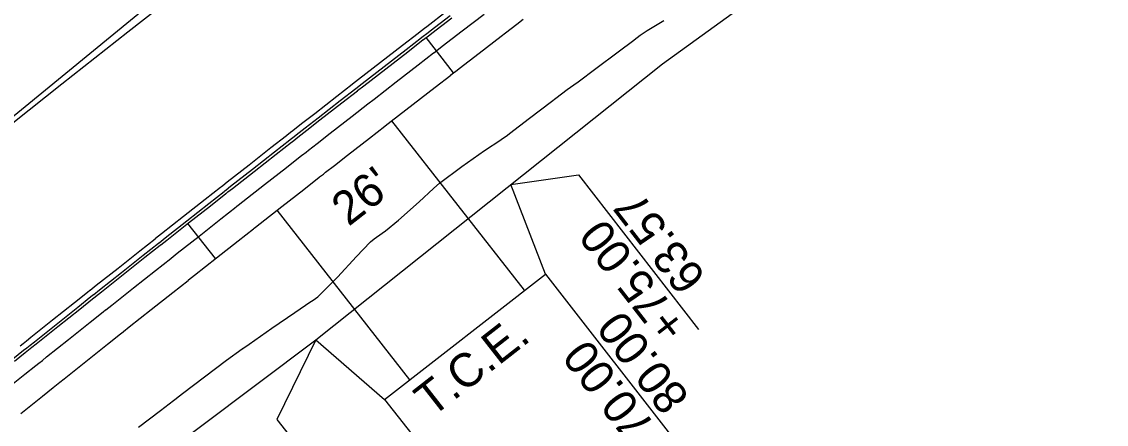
# Model space of a CAD drawing. Extents: x 1147550 to 1149124, y 2017436 to 2018779.
# Drawn here: x 1147906 to 1148099.8, y 2017688.9 to 2017760.9 of the extents above; entities that cross this region are included whole.
import ezdxf

# ---------------------------------------------------------------- set-up
doc = ezdxf.new("R2010")
doc.units = 0
for name, color, linetype in [('S_EDGE_CONCRETE', 7, 'Continuous'), ('S_ELECTRIC_UTILITIES', 7, 'Continuous'), ('S_HEADWALL', 7, 'Continuous'), ('S_IRON_PIN', 7, 'Continuous'), ('S_LANDSCAPING', 7, 'Continuous'), ('S_MAILBOX', 7, 'Continuous'), ('S_SECONDARY_CTL', 7, 'Continuous'), ('S_TELEPHONE_UTILITIES', 7, 'Continuous')]:
    doc.layers.add(name, color=color, linetype=linetype)

msp = doc.modelspace()

# ---------------------------------------------------------------- linework, layer by layer
at = {"layer": 'S_EDGE_CONCRETE'}
msp.add_line((1147825.51, 2017679.08), (1148011.14, 2017831.73), dxfattribs=at)
msp.add_arc((1151464.82, 2013253.76), 5729.58, 124.62946, 129.43332, dxfattribs=at)
at = {"layer": 'S_ELECTRIC_UTILITIES'}
msp.add_lwpolyline([(1147958.55, 2017704.02), (1147951.54, 2017689.76), (1147973.2, 2017662.27)], dxfattribs=at)
at = {"layer": 'S_HEADWALL'}
for p, q in [((1147983.15, 2017751.78), (1147978.22, 2017758.08)), ((1147995.8, 2017712.86), (1147972.09, 2017743.19)), ((1147975.31, 2017696.85), (1147951.6, 2017727.18)), ((1147940.6, 2017718.52), (1147935.68, 2017724.82))]:
    msp.add_line(p, q, dxfattribs=at)
at = {"layer": 'S_IRON_PIN'}
msp.add_line((1147958.55, 2017704.02), (1147970.81, 2017693.3), dxfattribs=at)
msp.add_lwpolyline([(1147970.81, 2017693.3), (1147999.55, 2017715.77), (1147993.38, 2017731.78)], dxfattribs=at)
at = {"layer": 'S_LANDSCAPING'}
for points in [[(1147993.38, 2017731.78), (1148005.46, 2017733.49), (1148026.91, 2017705.83)], [(1147999.55, 2017715.77), (1148024, 2017684.29)], [(1147970.81, 2017693.3), (1147994.96, 2017662.61)]]:
    msp.add_lwpolyline(points, dxfattribs=at)
at = {"layer": 'S_MAILBOX'}
msp.add_lwpolyline([(1147623.68, 2017436.42), (1147751.67, 2017548.43), (1147958.55, 2017704.02), (1148020.45, 2017753.36), (1148124.6, 2017828.73), (1148174.25, 2017853.51), (1148282.74, 2017941.53), (1148421.63, 2018031.39), (1148612.18, 2018197.22), (1148639.91, 2018214.06), (1148753.45, 2018306.48), (1148799.03, 2018350.69)], dxfattribs=at)
at = {"layer": 'S_SECONDARY_CTL'}
msp.add_lwpolyline([(1147926.82, 2017688.36), (1147930.75, 2017691.37), (1147933.11, 2017693.17), (1147933.56, 2017693.51), (1147933.62, 2017693.56), (1147934.69, 2017694.37), (1147938.63, 2017697.37), (1147942.56, 2017700.37), (1147945.37, 2017702.4), (1147945.45, 2017702.46), (1147945.46, 2017702.47), (1147946.6, 2017703.25), (1147950.68, 2017706.07), (1147954.77, 2017708.88), (1147957.64, 2017710.85), (1147957.77, 2017710.94), (1147958.03, 2017711.11), (1147958.86, 2017711.68), (1147962.39, 2017715.2), (1147965.77, 2017718.91), (1147968.21, 2017721.47), (1147968.29, 2017721.53), (1147968.96, 2017722.04), (1147969.37, 2017722.35), (1147970.99, 2017723.48), (1147973.28, 2017725.39), (1147976.97, 2017728.7), (1147979.57, 2017731.09), (1147979.6, 2017731.12), (1147980.63, 2017732.03), (1147980.65, 2017732.04), (1147984.6, 2017735.02), (1147988.66, 2017737.87), (1147991.59, 2017739.8), (1147991.65, 2017739.84), (1147992.77, 2017740.64), (1147993.15, 2017740.93), (1147996.71, 2017743.64), (1148000.65, 2017746.64), (1148001.44, 2017747.24), (1148003.45, 2017748.79), (1148003.45, 2017748.79), (1148004.61, 2017749.62), (1148005.41, 2017750.16), (1148008.59, 2017752.56), (1148012.55, 2017755.53), (1148015.33, 2017757.62), (1148015.4, 2017757.67), (1148016.51, 2017758.5), (1148017.72, 2017759.31), (1148020.73, 2017761.13)], dxfattribs=at)
at = {"layer": 'S_TELEPHONE_UTILITIES'}
for points in [[(1147905.67, 2017702.9), (1147906.24, 2017703.35), (1147906.85, 2017703.83), (1147907.62, 2017704.45), (1147911.5, 2017707.55), (1147915.39, 2017710.65), (1147917.72, 2017712.51), (1147918.17, 2017712.86), (1147918.23, 2017712.91), (1147919.28, 2017713.75), (1147923.18, 2017716.84), (1147927.07, 2017719.93), (1147929.79, 2017722.09), (1147929.87, 2017722.15), (1147929.88, 2017722.16), (1147930.97, 2017723.02), (1147934.87, 2017726.1), (1147938.78, 2017729.18), (1147941.52, 2017731.34), (1147941.65, 2017731.44), (1147941.89, 2017731.63), (1147942.68, 2017732.25), (1147946.59, 2017735.32), (1147950.5, 2017738.39), (1147953.27, 2017740.56), (1147953.35, 2017740.62), (1147954.01, 2017741.14), (1147954.42, 2017741.46), (1147955.99, 2017742.68), (1147958.34, 2017744.52), (1147962.26, 2017747.58), (1147965.05, 2017749.75), (1147965.08, 2017749.78), (1147966.16, 2017750.62), (1147966.18, 2017750.63), (1147970.11, 2017753.68), (1147974.03, 2017756.73), (1147976.81, 2017758.89), (1147976.87, 2017758.93), (1147977.97, 2017759.78), (1147978.34, 2017760.07), (1147981.9, 2017762.82)], [(1147902.67, 2017694.73), (1147906.55, 2017697.83), (1147908.49, 2017699.38), (1147909.05, 2017699.83), (1147909.66, 2017700.32), (1147910.43, 2017700.94), (1147914.31, 2017704.04), (1147918.19, 2017707.13), (1147920.52, 2017708.99), (1147920.97, 2017709.34), (1147921.03, 2017709.39), (1147922.08, 2017710.23), (1147925.97, 2017713.32), (1147929.87, 2017716.4), (1147932.59, 2017718.56), (1147932.66, 2017718.62), (1147932.68, 2017718.63), (1147933.76, 2017719.49), (1147937.66, 2017722.57), (1147941.56, 2017725.64), (1147944.3, 2017727.8), (1147944.43, 2017727.9), (1147944.67, 2017728.09), (1147945.46, 2017728.72), (1147949.37, 2017731.79), (1147953.28, 2017734.85), (1147956.05, 2017737.02), (1147956.12, 2017737.08), (1147956.79, 2017737.6), (1147957.19, 2017737.91), (1147958.76, 2017739.14), (1147961.11, 2017740.97), (1147965.02, 2017744.03), (1147967.81, 2017746.2), (1147967.84, 2017746.23), (1147968.93, 2017747.07), (1147968.94, 2017747.08), (1147972.87, 2017750.13), (1147976.79, 2017753.18), (1147979.57, 2017755.33), (1147979.62, 2017755.37), (1147980.72, 2017756.22), (1147981.09, 2017756.51), (1147984.65, 2017759.26), (1147988.58, 2017762.29)], [(1147904.36, 2017700.57), (1147906.3, 2017702.12), (1147906.86, 2017702.57), (1147907.47, 2017703.05), (1147908.24, 2017703.67), (1147912.13, 2017706.77), (1147916.01, 2017709.87), (1147918.34, 2017711.73), (1147918.79, 2017712.08), (1147918.85, 2017712.13), (1147919.9, 2017712.97), (1147923.8, 2017716.06), (1147927.69, 2017719.15), (1147930.41, 2017721.3), (1147930.49, 2017721.36), (1147930.51, 2017721.37), (1147931.59, 2017722.23), (1147935.49, 2017725.31), (1147939.4, 2017728.39), (1147942.13, 2017730.55), (1147942.26, 2017730.65), (1147942.51, 2017730.84), (1147943.3, 2017731.47), (1147947.21, 2017734.54), (1147951.12, 2017737.61), (1147953.89, 2017739.77), (1147953.96, 2017739.83), (1147954.63, 2017740.35), (1147955.04, 2017740.67), (1147956.6, 2017741.9), (1147958.95, 2017743.73), (1147962.87, 2017746.79), (1147965.66, 2017748.96), (1147965.69, 2017748.99), (1147966.78, 2017749.83), (1147966.79, 2017749.84), (1147970.72, 2017752.89), (1147974.65, 2017755.94), (1147977.43, 2017758.1), (1147977.48, 2017758.14), (1147978.58, 2017758.99), (1147978.95, 2017759.28), (1147982.51, 2017762.03)], [(1147904.67, 2017700.18), (1147906.61, 2017701.73), (1147907.17, 2017702.18), (1147907.78, 2017702.66), (1147908.55, 2017703.28), (1147912.44, 2017706.38), (1147916.33, 2017709.48), (1147918.65, 2017711.33), (1147919.1, 2017711.69), (1147919.16, 2017711.74), (1147920.22, 2017712.58), (1147924.11, 2017715.67), (1147928, 2017718.76), (1147930.72, 2017720.91), (1147930.8, 2017720.97), (1147930.82, 2017720.98), (1147931.9, 2017721.84), (1147935.8, 2017724.92), (1147939.7, 2017728), (1147942.44, 2017730.16), (1147942.57, 2017730.26), (1147942.82, 2017730.45), (1147943.61, 2017731.07), (1147947.52, 2017734.14), (1147951.43, 2017737.21), (1147954.2, 2017739.38), (1147954.27, 2017739.44), (1147954.94, 2017739.96), (1147955.34, 2017740.28), (1147956.91, 2017741.5), (1147959.26, 2017743.34), (1147963.18, 2017746.4), (1147965.97, 2017748.57), (1147966, 2017748.59), (1147967.09, 2017749.44), (1147967.1, 2017749.45), (1147971.03, 2017752.5), (1147974.95, 2017755.55), (1147977.73, 2017757.7), (1147977.78, 2017757.74), (1147978.88, 2017758.59), (1147979.26, 2017758.88), (1147982.82, 2017761.63)], [(1147905.8, 2017690.83), (1147909.67, 2017693.93), (1147911.61, 2017695.48), (1147912.17, 2017695.93), (1147912.78, 2017696.41), (1147913.55, 2017697.03), (1147917.43, 2017700.13), (1147921.31, 2017703.22), (1147923.64, 2017705.07), (1147924.08, 2017705.43), (1147924.14, 2017705.48), (1147925.19, 2017706.31), (1147929.08, 2017709.4), (1147932.97, 2017712.48), (1147935.69, 2017714.63), (1147935.76, 2017714.7), (1147935.78, 2017714.71), (1147936.86, 2017715.56), (1147940.76, 2017718.64), (1147944.66, 2017721.72), (1147947.39, 2017723.87), (1147947.52, 2017723.97), (1147947.77, 2017724.16), (1147948.56, 2017724.79), (1147952.46, 2017727.85), (1147956.36, 2017730.92), (1147959.13, 2017733.08), (1147959.2, 2017733.14), (1147959.87, 2017733.66), (1147960.27, 2017733.98), (1147961.84, 2017735.2), (1147964.18, 2017737.03), (1147968.1, 2017740.09), (1147970.88, 2017742.25), (1147970.91, 2017742.28), (1147972, 2017743.12), (1147972.01, 2017743.14), (1147975.93, 2017746.18), (1147979.85, 2017749.22), (1147982.63, 2017751.37), (1147982.68, 2017751.41), (1147983.78, 2017752.26), (1147984.15, 2017752.55), (1147987.71, 2017755.3), (1147991.64, 2017758.33), (1147992.42, 2017758.94), (1147994.43, 2017760.49), (1147994.44, 2017760.49), (1147995.57, 2017761.36)]]:
    msp.add_lwpolyline(points, dxfattribs=at)

# ---------------------------------------------------------------- texts
at = {"layer": 'S_HEADWALL'}
msp.add_text("26'", height=6, rotation=38.0135, dxfattribs=at).set_placement((1147964.38, 2017724.18))
at = {"layer": 'S_IRON_PIN'}
msp.add_text('T.C.E.', height=6, rotation=38.0185, dxfattribs=at).set_placement((1147979.25, 2017690))
at = {"layer": 'S_LANDSCAPING'}
for s, rotation, p in [('63.57', 127.7835, (1148028.46, 2017715.26)), ('+75.00', 127.7835, (1148025.14, 2017706.48)), ('80.00', 127.8335, (1148025.48, 2017693.79)), ('+70.00', 127.8335, (1148022.23, 2017684.93))]:
    msp.add_text(s, height=6, rotation=rotation, dxfattribs=at).set_placement(p)

doc.saveas('drawing.dxf')
